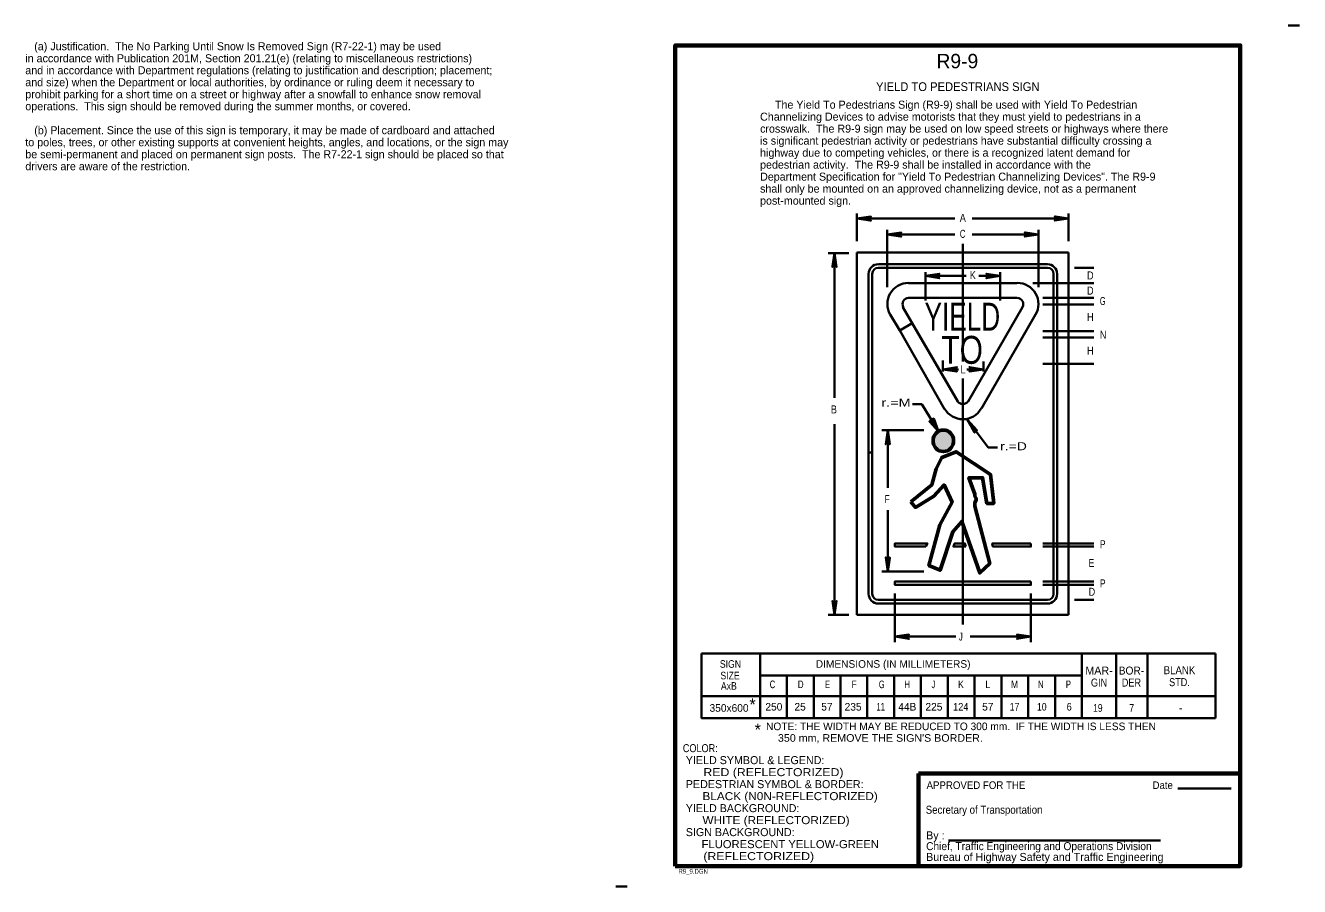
# Model space of a CAD drawing. Extents: x -0.203 to 0.195, y -0.006 to 0.263.
import ezdxf
from ezdxf.enums import TextEntityAlignment as Align

# ---------------------------------------------------------------- set-up
doc = ezdxf.new("R2010")
doc.units = 0
doc.header["$LTSCALE"] = 0.001
doc.linetypes.add('LONG_DASH_SHORT_DASH', pattern=[9.9, 6, -1.2, 1.5, -1.2])
for name, color, linetype, lineweight in [('1', 7, 'Continuous', 35), ('11', 7, 'Continuous', 35), ('12', 7, 'Continuous', 35), ('3', 7, 'Continuous', 35)]:
    doc.layers.add(name, color=color, linetype=linetype, lineweight=lineweight)
doc.layers.add('2', color=7, linetype='Continuous')

msp = doc.modelspace()

# ---------------------------------------------------------------- hatches: boundary and pattern name
at = {"layer": '12'}
h = msp.add_hatch(color=256, dxfattribs=at)
edge = h.paths.add_edge_path()
edge.add_ellipse((0.083745, 0.13294), major_axis=(0, 0.003361), ratio=0.9570313, start_angle=0, end_angle=360)

# ---------------------------------------------------------------- linework, layer by layer
at = {"layer": '1'}
for p, q in [((0.195, 0.26275), (0.1915, 0.26275)), ((0.157, 0.02425), (0.173625, 0.02425)), ((0.085375, 0.008), (0.151625, 0.008)), ((-0.015, -0.006375), (-0.0185, -0.006375))]:
    msp.add_line(p, q, dxfattribs=at)
at = {"layer": '1', "lineweight": 70}
for q in [(0.1765, 0.029), (0.076, 0)]:
    msp.add_line((0.076, 0.029), q, dxfattribs=at)
msp.add_lwpolyline([(0, 0), (0.1765, 0), (0.1765, 0.2565), (0, 0.2565)], close=True, dxfattribs=at)
at = {"layer": '11'}
for p, q in [((0.05675, 0.19175), (0.05675, 0.0785)), ((0.05675, 0.19175), (0.122875, 0.19175)), ((0.122875, 0.19175), (0.122875, 0.0785)), ((0.05675, 0.0785), (0.122875, 0.0785))]:
    msp.add_line(p, q, dxfattribs=at)
at = {"layer": '12'}
for p, q in [((0.0635, 0.188125), (0.11625, 0.188125)), ((0.11625, 0.187), (0.0635, 0.187)), ((0.118125, 0.085), (0.118125, 0.18525)), ((0.11925, 0.18525), (0.11925, 0.085)), ((0.10675, 0.18225), (0.072875, 0.18225)), ((0.072875, 0.177625), (0.10675, 0.177625)), ((0.1085, 0.17475), (0.0915, 0.14525)), ((0.095625, 0.143), (0.1125, 0.172375)), ((0.08825, 0.14525), (0.074, 0.16975)), ((0.060375, 0.085), (0.060375, 0.12925)), ((0.0635, 0.08325), (0.11625, 0.08325)), ((0.11625, 0.082125), (0.0635, 0.082125))]:
    msp.add_line(p, q, dxfattribs=at)
for points in [[(0.0615, 0.18525), (0.0615, 0.12925), (0.060375, 0.12925), (0.060375, 0.18525)], [(0.067125, 0.172375), (0.070125, 0.167375), (0.074, 0.16975), (0.071125, 0.17475)], [(0.074, 0.16975), (0.070125, 0.167375), (0.084125, 0.142875)], [(0.060375, 0.12925), (0.0615, 0.12925), (0.0615, 0.085)]]:
    msp.add_lwpolyline(points, dxfattribs=at)
at = {"layer": '12', "lineweight": 60}
msp.add_lwpolyline([(0.073625, 0.113875), (0.075, 0.112125), (0.08075, 0.115625), (0.084, 0.119125), (0.0865, 0.11375), (0.082625, 0.106625), (0.07925, 0.094), (0.08275, 0.0925), (0.08675, 0.1045), (0.0895, 0.10775), (0.095125, 0.091625), (0.09825, 0.094625), (0.093625, 0.1125), (0.093625, 0.1135), (0.094, 0.1145), (0.094, 0.114875), (0.093625, 0.115625), (0.093625, 0.11625), (0.09175, 0.121375), (0.096, 0.121375), (0.097375, 0.113375), (0.0995, 0.113375), (0.0985, 0.122375), (0.08775, 0.1295), (0.085125, 0.1285), (0.08325, 0.12775), (0.0815, 0.124125), (0.080125, 0.119125)], close=True, dxfattribs=at)
at = {"layer": '12'}
for points in [[(0.07825, 0.099875), (0.068625, 0.099875), (0.068625, 0.100875), (0.07875, 0.100875)], [(0.09075, 0.099875), (0.086875, 0.099875), (0.08725, 0.100875), (0.0905, 0.100875)], [(0.111125, 0.100875), (0.099, 0.100875), (0.09925, 0.099875), (0.111125, 0.099875)], [(0.111125, 0.089), (0.068625, 0.089), (0.068625, 0.087875), (0.111125, 0.087875)]]:
    msp.add_lwpolyline(points, close=True, dxfattribs=at)
for centre, radius, start, end in [((0.063434, 0.185123), 0.003012, 90, 180), ((0.116282, 0.185123), 0.003012, 0, 90), ((0.063434, 0.185123), 0.001887, 90, 180), ((0.116282, 0.185123), 0.001887, 0, 90), ((0.072871, 0.175686), 0.006606, 90, 210.01589), ((0.106845, 0.175686), 0.006606, 329.98411, 90), ((0.072883, 0.175686), 0.001887, 90, 209.941), ((0.106833, 0.175686), 0.001887, 330.059, 90), ((0.089852, 0.146295), 0.001887, 210.10833, 330.06549), ((0.089852, 0.146295), 0.006606, 210.10832, 330.06549), ((0.063434, 0.085089), 0.003012, 180, 270), ((0.063434, 0.085089), 0.001887, 180, 270), ((0.116282, 0.085089), 0.001887, 270, 0), ((0.116282, 0.085089), 0.003012, 270, 0)]:
    msp.add_arc(centre, radius, start, end, dxfattribs=at)
at = {"layer": '12', "lineweight": 60}
msp.add_ellipse((0.083745, 0.13294), major_axis=(0, 0.003361), ratio=0.957031, dxfattribs=at)
at = {"layer": '3'}
for p, q in [((0.05675, 0.204), (0.05675, 0.195375)), ((0.122875, 0.204), (0.122875, 0.195375)), ((0.05675, 0.202375), (0.087375, 0.202375)), ((0.09275, 0.202375), (0.122875, 0.202375)), ((0.06625, 0.198875), (0.06625, 0.181)), ((0.06625, 0.197375), (0.087375, 0.197375)), ((0.09275, 0.197375), (0.1135, 0.197375)), ((0.1135, 0.198875), (0.1135, 0.181)), ((0.05425, 0.191625), (0.04775, 0.191625)), ((0.04975, 0.191625), (0.04975, 0.146375)), ((0.078125, 0.185625), (0.078125, 0.17675)), ((0.078125, 0.1845), (0.090875, 0.1845)), ((0.094875, 0.1845), (0.1015, 0.1845)), ((0.1015, 0.185625), (0.1015, 0.17675)), ((0.12475, 0.187), (0.13075, 0.187)), ((0.11175, 0.18225), (0.13075, 0.18225)), ((0.114875, 0.177625), (0.13075, 0.177625)), ((0.114875, 0.1755), (0.13075, 0.1755)), ((0.114875, 0.16725), (0.13075, 0.16725)), ((0.114875, 0.16525), (0.13075, 0.16525)), ((0.083625, 0.158), (0.083625, 0.154625)), ((0.083625, 0.15525), (0.0885, 0.15525)), ((0.091125, 0.15525), (0.09625, 0.15525)), ((0.09625, 0.15775), (0.09625, 0.154625)), ((0.114875, 0.157), (0.13075, 0.157)), ((0.077, 0.144375), (0.074125, 0.144375)), ((0.077, 0.144375), (0.08225, 0.135875)), ((0.09125, 0.1395), (0.09775, 0.130875)), ((0.09125, 0.1395), (0.0935, 0.136125)), ((0.04975, 0.138125), (0.04975, 0.0785)), ((0.0645, 0.13625), (0.077625, 0.13625)), ((0.066375, 0.13625), (0.066375, 0.11825)), ((0.09775, 0.130875), (0.100625, 0.130875)), ((0.066375, 0.11125), (0.066375, 0.092125)), ((0.114875, 0.100875), (0.13075, 0.100875)), ((0.114875, 0.099875), (0.13075, 0.099875)), ((0.0645, 0.092125), (0.077625, 0.092125)), ((0.114875, 0.089), (0.13075, 0.089)), ((0.114875, 0.087875), (0.13075, 0.087875)), ((0.068625, 0.08525), (0.068625, 0.07)), ((0.111125, 0.08525), (0.111125, 0.07)), ((0.12475, 0.08325), (0.13075, 0.08325)), ((0.05425, 0.0785), (0.04775, 0.0785)), ((0.068625, 0.07175), (0.087625, 0.07175)), ((0.111125, 0.07175), (0.092125, 0.07175)), ((0.00825, 0.0665), (0.16875, 0.0665)), ((0.0265, 0.0665), (0.0265, 0.04625)), ((0.127, 0.0665), (0.127, 0.04625)), ((0.13775, 0.066625), (0.13775, 0.046375)), ((0.1475, 0.0665), (0.1475, 0.04625)), ((0.16875, 0.0665), (0.16875, 0.04625)), ((0.127, 0.059625), (0.0265, 0.059625)), ((0.034875, 0.059625), (0.034875, 0.04625)), ((0.04325, 0.059625), (0.04325, 0.04625)), ((0.051625, 0.059625), (0.051625, 0.04625)), ((0.06, 0.059625), (0.06, 0.04625)), ((0.068375, 0.059625), (0.068375, 0.04625)), ((0.07675, 0.059625), (0.07675, 0.04625)), ((0.085125, 0.059625), (0.085125, 0.04625)), ((0.0935, 0.059625), (0.0935, 0.04625)), ((0.101875, 0.059625), (0.101875, 0.04625)), ((0.11025, 0.059625), (0.11025, 0.04625)), ((0.118625, 0.059625), (0.118625, 0.04625)), ((0.00825, 0.053125), (0.16875, 0.053125))]:
    msp.add_line(p, q, dxfattribs=at)
at = {"layer": '3', "linetype": 'LONG_DASH_SHORT_DASH'}
for p, q in [((0.089875, 0.1945), (0.089875, 0.15775)), ((0.089875, 0.152375), (0.089875, 0.0755))]:
    msp.add_line(p, q, dxfattribs=at)
at = {"layer": '3'}
for points in [[(0.060875, 0.20175), (0.06075, 0.202125), (0.05675, 0.202375), (0.060875, 0.20175), (0.061125, 0.20175), (0.05675, 0.202375), (0.06075, 0.202625), (0.060875, 0.202875), (0.05675, 0.202375), (0.061125, 0.203), (0.060875, 0.202875)], [(0.11875, 0.203), (0.11875, 0.202625), (0.122875, 0.202375), (0.11875, 0.203), (0.1185, 0.203), (0.122875, 0.202375), (0.11875, 0.202125), (0.11875, 0.201875), (0.122875, 0.202375), (0.1185, 0.20175), (0.11875, 0.201875)], [(0.070375, 0.19675), (0.07025, 0.197125), (0.06625, 0.197375), (0.070375, 0.19675), (0.070625, 0.19675), (0.06625, 0.197375), (0.07025, 0.197625), (0.070375, 0.197875), (0.06625, 0.197375), (0.070625, 0.198), (0.070375, 0.197875)], [(0.109375, 0.198), (0.109375, 0.197625), (0.1135, 0.197375), (0.109375, 0.198), (0.109125, 0.198), (0.1135, 0.197375), (0.109375, 0.197125), (0.109375, 0.196875), (0.1135, 0.197375), (0.109125, 0.19675), (0.109375, 0.196875)], [(0.049125, 0.1875), (0.0495, 0.187625), (0.04975, 0.191625), (0.049125, 0.1875), (0.049125, 0.18725), (0.04975, 0.191625), (0.05, 0.187625), (0.05025, 0.1875), (0.04975, 0.191625), (0.050375, 0.18725), (0.05025, 0.1875)], [(0.08225, 0.183875), (0.082125, 0.18425), (0.078125, 0.1845), (0.08225, 0.183875), (0.0825, 0.18375), (0.078125, 0.1845), (0.082125, 0.184625), (0.08225, 0.184875), (0.078125, 0.1845), (0.0825, 0.185125), (0.08225, 0.184875)], [(0.097375, 0.185), (0.0975, 0.184625), (0.1015, 0.1845), (0.097375, 0.185), (0.097125, 0.185125), (0.1015, 0.1845), (0.0975, 0.18425), (0.097375, 0.184), (0.1015, 0.1845), (0.097125, 0.18375), (0.097375, 0.184)], [(0.08775, 0.15475), (0.087625, 0.155125), (0.083625, 0.15525), (0.08775, 0.15475), (0.088, 0.154625), (0.083625, 0.15525), (0.087625, 0.1555), (0.08775, 0.15575), (0.083625, 0.15525), (0.088, 0.156), (0.08775, 0.15575)], [(0.092125, 0.155875), (0.09225, 0.1555), (0.09625, 0.15525), (0.092125, 0.155875), (0.091875, 0.156), (0.09625, 0.15525), (0.09225, 0.155125), (0.092125, 0.154875), (0.09625, 0.15525), (0.091875, 0.154625), (0.092125, 0.154875)], [(0.079375, 0.139), (0.07975, 0.139125), (0.08225, 0.135875), (0.079375, 0.139), (0.079875, 0.139375), (0.08225, 0.135875), (0.080125, 0.139375), (0.08025, 0.13975), (0.08225, 0.135875), (0.08075, 0.139875), (0.08025, 0.13975)], [(0.0935, 0.13575), (0.093375, 0.136), (0.09125, 0.1395), (0.0935, 0.13575), (0.0935, 0.1355), (0.09125, 0.1395), (0.09375, 0.136375), (0.094, 0.136375), (0.09125, 0.1395), (0.09425, 0.13625), (0.094, 0.136375)], [(0.065875, 0.132125), (0.066125, 0.13225), (0.066375, 0.13625), (0.065875, 0.132125), (0.06575, 0.131875), (0.066375, 0.13625), (0.066625, 0.13225), (0.066875, 0.132125), (0.066375, 0.13625), (0.067, 0.131875), (0.066875, 0.132125)], [(0.067, 0.09625), (0.066625, 0.096125), (0.066375, 0.092125), (0.067, 0.09625), (0.067, 0.0965), (0.066375, 0.092125), (0.066125, 0.096125), (0.066, 0.09625), (0.066375, 0.092125), (0.06575, 0.0965), (0.066, 0.09625)], [(0.05025, 0.082625), (0.05, 0.0825), (0.04975, 0.0785), (0.05025, 0.082625), (0.050375, 0.082875), (0.04975, 0.0785), (0.0495, 0.0825), (0.04925, 0.082625), (0.04975, 0.0785), (0.049125, 0.082875), (0.04925, 0.082625)], [(0.07275, 0.071125), (0.072625, 0.0715), (0.068625, 0.07175), (0.07275, 0.071125), (0.073, 0.071), (0.068625, 0.07175), (0.072625, 0.071875), (0.07275, 0.072125), (0.068625, 0.07175), (0.073, 0.072375), (0.07275, 0.072125)], [(0.107, 0.071125), (0.107125, 0.0715), (0.111125, 0.07175), (0.107, 0.071125), (0.10675, 0.071), (0.111125, 0.07175), (0.107125, 0.071875), (0.107, 0.072125), (0.111125, 0.07175), (0.10675, 0.072375), (0.107, 0.072125)], [(0.00825, 0.0665), (0.00825, 0.04625), (0.16875, 0.04625)]]:
    msp.add_lwpolyline(points, dxfattribs=at)

# ---------------------------------------------------------------- texts
at = {"layer": '1'}
msp.add_text('R9-9', height=0.0045, dxfattribs=at).set_placement((0.088125, 0.249375), align=Align.CENTER)
at = {"layer": '1', "width": 0.95}
for s, height, p in [('YIELD TO PEDESTRIANS SIGN', 0.00275, (0.08825, 0.24225)), ('APPROVED FOR THE', 0.002375, (0.093938, 0.024125)), ('Date ', 0.002375, (0.152688, 0.024125))]:
    msp.add_text(s, height=height, dxfattribs=at).set_placement(p, align=Align.CENTER)
at = {"layer": '1'}
for s, height, width, p in [('COLOR: ', 0.0025, 0.85, (0.002375, 0.035625)), ('      RED (REFLECTORIZED)', 0.0025, 1.15, (0.002375, 0.028125)), ('      BLACK (N0N-REFLECTORIZED)', 0.0025, 1.1, (0.002375, 0.020625)), ('Secretary of Transportation', 0.0025, 0.9, (0.07825, 0.016375)), ('      WHITE (REFLECTORIZED)', 0.0025, 1.1, (0.002375, 0.013125)), ('      FLUORESCENT YELLOW-GREEN', 0.0025, 1.05, (0.002375, 0.005625)), ('      (REFLECTORIZED)', 0.0025, 1.15, (0.002375, 0.001875)), ('Chief, Traffic Engineering and Operations Division', 0.0025, 0.95, (0.078375, 0.005)), ('R9_9.DGN', 0.0015, 0.75, (0.001, -0.002375))]:
    msp.add_text(s, height=height, dxfattribs=dict(at, width=width)).set_placement(p)
for s, p in [(' YIELD SYMBOL & LEGEND:', (0.002375, 0.031875)), (' PEDESTRIAN SYMBOL & BORDER:', (0.002375, 0.024375)), (' YIELD BACKGROUND:', (0.002375, 0.016875)), (' SIGN BACKGROUND:', (0.002375, 0.009375)), ('By :', (0.078375, 0.008375)), ('Bureau of Highway Safety and Traffic Engineering', (0.078375, 0.001625))]:
    msp.add_text(s, height=0.0025, dxfattribs=at).set_placement(p)
at = {"layer": '12'}
for s, width, p in [('YIELD', 0.7, (0.089688, 0.167375)), ('TO', 0.8, (0.089625, 0.157))]:
    msp.add_text(s, height=0.008727, dxfattribs=dict(at, width=width)).set_placement(p, align=Align.CENTER)
at = {"layer": '2'}
for s, p in [('   (a) Justification.  The No Parking Until Snow Is Removed Sign (R7-22-1) may be used', (-0.203, 0.255)), ('in accordance with Publication 201M, Section 201.21(e) (relating to miscellaneous restrictions)', (-0.203, 0.25125)), ('and in accordance with Department regulations (relating to justification and description; placement;', (-0.203, 0.2475)), ('and size) when the Department or local authorities, by ordinance or ruling deem it necessary to', (-0.203, 0.24375)), ('operations.  This sign should be removed during the summer months, or covered.', (-0.203, 0.23625)), ('prohibit parking for a short time on a street or highway after a snowfall to enhance snow removal', (-0.203, 0.24)), ('   (b) Placement. Since the use of this sign is temporary, it may be made of cardboard and attached', (-0.203, 0.22875)), ('to poles, trees, or other existing supports at convenient heights, angles, and locations, or the sign may', (-0.203, 0.225)), ('be semi-permanent and placed on permanent sign posts.  The R7-22-1 sign should be placed so that', (-0.203, 0.22125)), ('drivers are aware of the restriction.', (-0.203, 0.2175))]:
    msp.add_text(s, height=0.0025, dxfattribs=at).set_placement(p)
at = {"layer": '3'}
for s, height, p in [('     The Yield To Pedestrians Sign (R9-9) shall be used with Yield To Pedestrian', 0.0025, (0.0265, 0.23675)), ('Channelizing Devices to advise motorists that they must yield to pedestrians in a', 0.0025, (0.0265, 0.233)), ('crosswalk.  The R9-9 sign may be used on low speed streets or highways where there', 0.0025, (0.0265, 0.22925)), ('is significant pedestrian activity or pedestrians have substantial difficulty crossing a', 0.0025, (0.0265, 0.2255)), ('highway due to competing vehicles, or there is a recognized latent demand for', 0.0025, (0.0265, 0.22175)), ('pedestrian activity.  The R9-9 shall be installed in accordance with the', 0.0025, (0.0265, 0.218)), ('Department Specification for "Yield To Pedestrian Channelizing Devices". The R9-9', 0.0025, (0.0265, 0.21425)), ('shall only be mounted on an approved channelizing device, not as a permanent', 0.0025, (0.0265, 0.2105)), ('post-mounted sign.', 0.0025, (0.0265, 0.20675)), ('NOTE: THE WIDTH MAY BE REDUCED TO 300 mm.  IF THE WIDTH IS LESS THEN', 0.002375, (0.028375, 0.0425))]:
    msp.add_text(s, height=height, dxfattribs=at).set_placement(p)
for s, height, width, p in [('A', 0.0025, 0.85, (0.088875, 0.201375)), ('C', 0.0025, 0.75, (0.088875, 0.196375)), ('K', 0.0025, 0.85, (0.092, 0.1835)), ('D', 0.0025, 0.85, (0.128625, 0.183375)), ('D', 0.0025, 0.85, (0.128625, 0.178625)), ('G', 0.0025, 0.7, (0.132625, 0.175375)), ('H', 0.0025, 0.85, (0.128625, 0.170375)), ('N', 0.0025, 0.85, (0.132625, 0.164875)), ('H', 0.0025, 0.85, (0.128625, 0.159875)), ('L', 0.0025, 0.85, (0.089125, 0.154)), ('B', 0.0025, 0.85, (0.048625, 0.1415)), ('r.=M', 0.0025, 1.35, (0.064375, 0.143625)), ('r.=D', 0.0025, 1.3, (0.1015, 0.13)), ('F', 0.0025, 0.8, (0.065375, 0.1135)), ('P', 0.0025, 0.8, (0.132625, 0.099375)), ('E', 0.0025, 0.8, (0.129125, 0.0935)), ('P', 0.0025, 0.8, (0.132625, 0.087125)), ('D', 0.0025, 0.85, (0.129125, 0.0845)), ('J', 0.0025, 0.65, (0.088625, 0.0705)), ("    350 mm, REMOVE THE SIGN'S BORDER.", 0.002375, 1.05, (0.028375, 0.038875))]:
    msp.add_text(s, height=height, dxfattribs=dict(at, width=width)).set_placement(p)
for s, height, width, p in [('SIGN', 0.002375, 0.85, (0.01725, 0.062)), ('SIZE', 0.002375, 0.85, (0.017125, 0.058375)), ('BOR-', 0.0025, 0.95, (0.1425, 0.059875)), ('BLANK', 0.0025, 0.9, (0.1575, 0.06)), ('AxB', 0.002375, 0.85, (0.01675, 0.055125)), ('C', 0.002375, 0.75, (0.030375, 0.055625)), ('D', 0.002375, 0.8, (0.039188, 0.055625)), ('E', 0.002375, 0.75, (0.047563, 0.055625)), ('F', 0.002375, 0.8, (0.055875, 0.055625)), ('G', 0.002375, 0.7, (0.0645, 0.055625)), ('H', 0.002375, 0.8, (0.072438, 0.055625)), ('J', 0.002375, 0.65, (0.080625, 0.055625)), ('K', 0.002375, 0.85, (0.08925, 0.055625)), ('L', 0.002375, 0.85, (0.097625, 0.055625)), ('M', 0.002375, 0.85, (0.106, 0.055625)), ('N', 0.002375, 0.8, (0.114187, 0.055625)), ('P', 0.002375, 0.75, (0.122813, 0.055625)), ('GIN', 0.0025, 0.85, (0.132375, 0.056125)), ('DER', 0.0025, 0.85, (0.1425, 0.056125)), ('STD.', 0.0025, 0.85, (0.1575, 0.05625)), ('11', 0.002375, 0.75, (0.064187, 0.048625)), ('124', 0.002375, 0.9, (0.089188, 0.048625)), ('17', 0.002375, 0.85, (0.106, 0.048625)), ('10', 0.002375, 0.85, (0.1145, 0.048625)), ('6', 0.002375, 0.9, (0.123063, 0.048625)), ('19', 0.002375, 0.85, (0.132, 0.04825)), ('7', 0.002375, 0.9, (0.142563, 0.04825))]:
    msp.add_text(s, height=height, dxfattribs=dict(at, width=width)).set_placement(p, align=Align.CENTER)
for s, height, p in [('DIMENSIONS (IN MILLIMETERS)', 0.002375, (0.068062, 0.062)), ('MAR-', 0.0025, (0.132375, 0.059875)), ('350x600', 0.002375, (0.016813, 0.04825)), ('250', 0.002375, (0.030812, 0.048625)), ('25', 0.002375, (0.039, 0.048625)), ('57', 0.002375, (0.047375, 0.048625)), ('235', 0.002375, (0.055563, 0.048625)), ('44B', 0.002375, (0.0725, 0.048625)), ('225', 0.002375, (0.080812, 0.048625)), ('57', 0.002375, (0.097625, 0.048625)), ('-', 0.002375, (0.157875, 0.04825))]:
    msp.add_text(s, height=height, dxfattribs=at).set_placement(p, align=Align.CENTER)
for p in [(0.024217, 0.048644), (0.025842, 0.040769)]:
    msp.add_text('*', height=0.003778, rotation=1, dxfattribs=at).set_placement(p, align=Align.CENTER)

doc.saveas('drawing.dxf')
